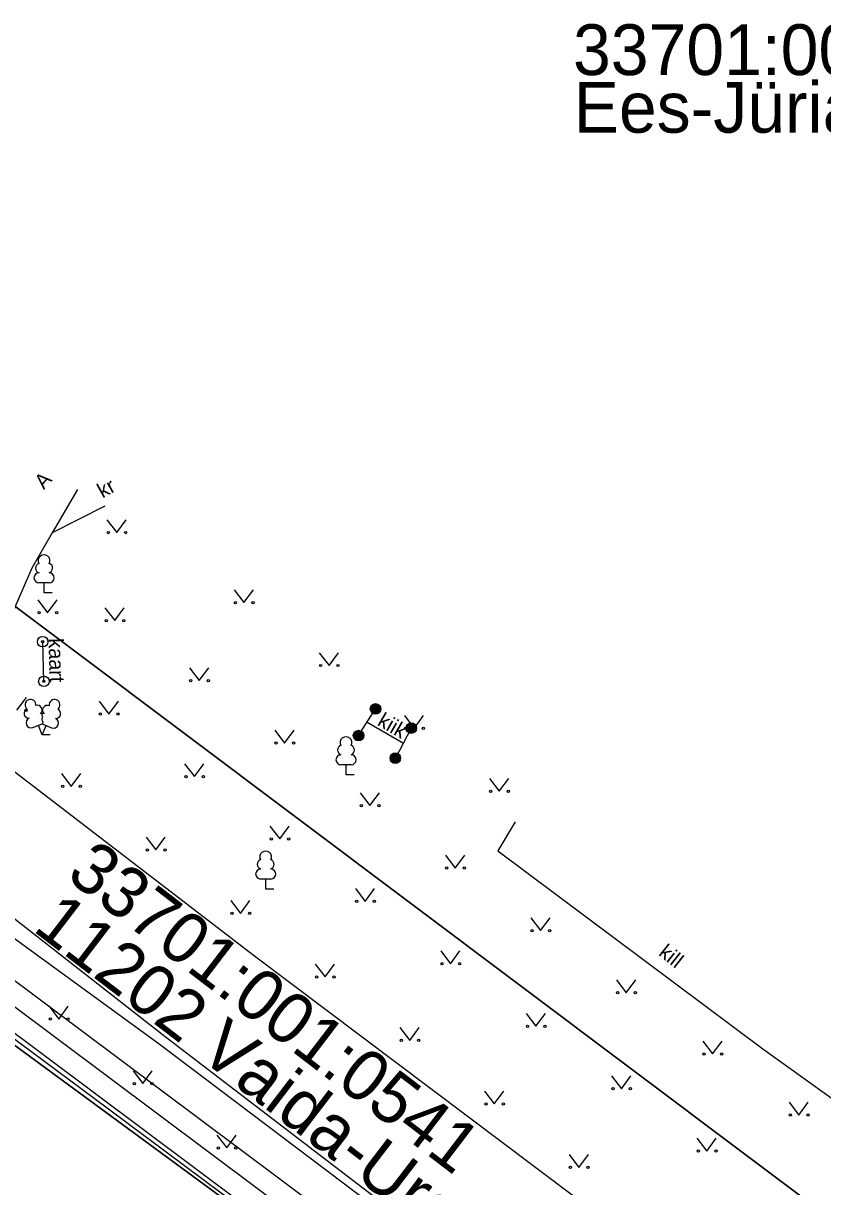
# Model space of a CAD drawing. Extents: x 554947 to 555436, y 6564938 to 6565792.
# Drawn here: x 555270.1 to 555307.9, y 6565557.2 to 6565612.2 of the extents above; entities that cross this region are included whole.
import ezdxf

# ---------------------------------------------------------------- set-up
doc = ezdxf.new("R2010")
doc.units = 0
for name, color, linetype in [('AED', 7, 'Continuous'), ('HALJASTUS', 7, 'Continuous'), ('KASUTUSALA', 7, 'Continuous'), ('LIIKLUS', 7, 'Continuous'), ('PIIR', 7, 'Continuous'), ('POST', 7, 'Continuous'), ('PR_SIDE', 7, 'Continuous'), ('PUU', 7, 'Continuous'), ('TEE', 7, 'Continuous')]:
    doc.layers.add(name, color=color, linetype=linetype)

msp = doc.modelspace()

# ---------------------------------------------------------------- linework, layer by layer
at = {"layer": 'AED'}
msp.add_lwpolyline([(555301.646, 6565540.531), (555292.158, 6565547.42), (555274.134, 6565560.859), (555261.407, 6565570.297)], dxfattribs=at)
at = {"layer": 'HALJASTUS'}
for p, q in [((555274.065, 6565588.705), (555274.529, 6565588.099)), ((555274.529, 6565588.099), (555274.974, 6565588.705)), ((555280.082, 6565585.392), (555280.545, 6565584.785)), ((555280.545, 6565584.785), (555280.991, 6565585.392)), ((555270.802, 6565584.917), (555271.265, 6565584.311)), ((555271.265, 6565584.311), (555271.711, 6565584.917)), ((555273.975, 6565584.54), (555274.438, 6565583.934)), ((555274.438, 6565583.934), (555274.884, 6565584.54)), ((555284.104, 6565582.421), (555284.567, 6565581.815)), ((555284.567, 6565581.815), (555285.013, 6565582.421)), ((555277.967, 6565581.711), (555278.43, 6565581.104)), ((555278.43, 6565581.104), (555278.876, 6565581.711)), ((555269.814, 6565579.699), (555270.26, 6565580.306)), ((555273.698, 6565580.126), (555274.162, 6565579.519)), ((555274.162, 6565579.519), (555274.607, 6565580.126)), ((555288.126, 6565579.451), (555288.589, 6565578.844)), ((555288.589, 6565578.844), (555289.035, 6565579.451)), ((555282.001, 6565578.757), (555282.464, 6565578.15)), ((555282.464, 6565578.15), (555282.91, 6565578.757)), ((555277.735, 6565577.176), (555278.199, 6565576.569)), ((555278.199, 6565576.569), (555278.644, 6565577.176)), ((555271.917, 6565576.711), (555272.38, 6565576.104)), ((555272.38, 6565576.104), (555272.826, 6565576.711)), ((555292.148, 6565576.481), (555292.611, 6565575.874)), ((555292.611, 6565575.874), (555293.057, 6565576.481)), ((555286.035, 6565575.803), (555286.499, 6565575.196)), ((555286.499, 6565575.196), (555286.944, 6565575.803)), ((555281.772, 6565574.226), (555282.236, 6565573.619)), ((555282.236, 6565573.619), (555282.681, 6565574.226)), ((555275.916, 6565573.71), (555276.38, 6565573.104)), ((555276.38, 6565573.104), (555276.825, 6565573.71)), ((555290.069, 6565572.849), (555290.533, 6565572.243)), ((555290.533, 6565572.243), (555290.978, 6565572.849)), ((555285.809, 6565571.276), (555286.273, 6565570.669)), ((555286.273, 6565570.669), (555286.718, 6565571.276)), ((555279.916, 6565570.71), (555280.379, 6565570.103)), ((555280.379, 6565570.103), (555280.825, 6565570.71)), ((555294.104, 6565569.895), (555294.567, 6565569.289)), ((555294.567, 6565569.289), (555295.013, 6565569.895)), ((555289.846, 6565568.326), (555290.31, 6565567.719)), ((555290.31, 6565567.719), (555290.755, 6565568.326)), ((555283.915, 6565567.709), (555284.379, 6565567.102)), ((555284.379, 6565567.102), (555284.824, 6565567.709)), ((555298.15, 6565566.958), (555298.613, 6565566.351)), ((555298.613, 6565566.351), (555299.059, 6565566.958)), ((555271.333, 6565565.713), (555271.796, 6565565.106)), ((555271.796, 6565565.106), (555272.242, 6565565.713)), ((555293.883, 6565565.376), (555294.347, 6565564.769)), ((555294.347, 6565564.769), (555294.792, 6565565.376)), ((555287.915, 6565564.708), (555288.378, 6565564.102)), ((555288.378, 6565564.102), (555288.824, 6565564.708)), ((555302.23, 6565564.068), (555302.693, 6565563.461)), ((555302.693, 6565563.461), (555303.139, 6565564.068)), ((555275.3, 6565562.67), (555275.764, 6565562.063)), ((555275.764, 6565562.063), (555276.209, 6565562.67)), ((555297.92, 6565562.426), (555298.384, 6565561.819)), ((555298.384, 6565561.819), (555298.829, 6565562.426)), ((555291.914, 6565561.708), (555292.378, 6565561.101)), ((555292.378, 6565561.101), (555292.823, 6565561.708)), ((555306.31, 6565561.178), (555306.773, 6565560.571)), ((555306.773, 6565560.571), (555307.219, 6565561.178)), ((555279.268, 6565559.627), (555279.731, 6565559.02)), ((555279.731, 6565559.02), (555280.177, 6565559.627)), ((555301.957, 6565559.476), (555302.421, 6565558.869)), ((555302.421, 6565558.869), (555302.866, 6565559.476)), ((555295.914, 6565558.707), (555296.377, 6565558.1)), ((555296.377, 6565558.1), (555296.823, 6565558.707))]:
    msp.add_line(p, q, dxfattribs=at)
for centre in [(555274.128, 6565588.099), (555274.956, 6565588.099), (555280.144, 6565584.785), (555280.973, 6565584.785), (555270.864, 6565584.311), (555271.693, 6565584.311), (555274.037, 6565583.934), (555274.866, 6565583.934), (555284.166, 6565581.815), (555284.995, 6565581.815), (555278.029, 6565581.104), (555278.858, 6565581.104), (555270.242, 6565579.699), (555273.761, 6565579.519), (555274.589, 6565579.519), (555288.188, 6565578.844), (555289.017, 6565578.844), (555282.063, 6565578.15), (555282.892, 6565578.15), (555277.798, 6565576.569), (555278.626, 6565576.569), (555271.979, 6565576.104), (555272.808, 6565576.104), (555292.21, 6565575.874), (555293.039, 6565575.874), (555286.098, 6565575.196), (555286.926, 6565575.196), (555281.835, 6565573.619), (555282.663, 6565573.619), (555275.979, 6565573.104), (555276.807, 6565573.104), (555290.132, 6565572.243), (555290.961, 6565572.243), (555285.872, 6565570.669), (555286.7, 6565570.669), (555279.978, 6565570.103), (555280.807, 6565570.103), (555294.166, 6565569.289), (555294.995, 6565569.289), (555289.909, 6565567.719), (555290.737, 6565567.719), (555283.978, 6565567.102), (555284.806, 6565567.102), (555298.212, 6565566.351), (555299.041, 6565566.351), (555271.395, 6565565.106), (555272.224, 6565565.106), (555293.946, 6565564.769), (555294.774, 6565564.769), (555287.977, 6565564.102), (555288.806, 6565564.102), (555302.292, 6565563.461), (555303.121, 6565563.461), (555275.363, 6565562.063), (555276.192, 6565562.063), (555297.983, 6565561.819), (555298.811, 6565561.819), (555291.977, 6565561.101), (555292.805, 6565561.101), (555306.372, 6565560.571), (555307.201, 6565560.571), (555279.33, 6565559.02), (555280.159, 6565559.02), (555302.02, 6565558.869), (555302.849, 6565558.869), (555295.976, 6565558.1), (555296.805, 6565558.1)]:
    msp.add_circle(centre, 0.055, dxfattribs=at)
at = {"layer": 'KASUTUSALA'}
msp.add_lwpolyline([(555282.937, 6565554.541), (555264.078, 6565568.633), (555259.865, 6565571.933), (555249.017, 6565580.573), (555243.622, 6565583.862), (555238.34, 6565585.678), (555238.34, 6565584.092), (555236.34, 6565584.168), (555236.34, 6565586.946), (555231.217, 6565605.702), (555233.309, 6565605.634), (555234.35, 6565605.6), (555235.803, 6565604.987), (555234.66, 6565604.12), (555233.701, 6565604.199), (555238.103, 6565588.08), (555238.166, 6565587.854), (555238.34, 6565587.793), (555244.478, 6565585.683), (555250.166, 6565582.216), (555261.104, 6565573.503), (555265.293, 6565570.221), (555284.174, 6565556.114)], dxfattribs=at)
at = {"layer": 'LIIKLUS'}
msp.add_line((555271.087, 6565581.066), (555271.031, 6565582.94), dxfattribs=at)
for centre, radius in [((555271.031, 6565582.94), 0.25), ((555271.031, 6565582.94), 0.05), ((555271.087, 6565581.066), 0.25), ((555271.087, 6565581.066), 0.05)]:
    msp.add_circle(centre, radius, dxfattribs=at)
at = {"layer": 'PIIR'}
for points in [[(555374.15, 6565660.24), (555410.9, 6565638.65), (555418.94, 6565635.85), (555435.71, 6565632.72), (555428.83, 6565620.98), (555419.65, 6565609.54), (555361.56, 6565549.57), (555350.68, 6565540.44), (555343.81, 6565536.56), (555330.71, 6565538.85), (555251.24, 6565598.48), (555234.35, 6565605.6), (555223.17, 6565668.21)], [(555144.16, 6565410.6), (555124.27, 6565454.45), (555113.82, 6565475.68), (555076.76, 6565542.38), (555065.78, 6565566.7), (555060.42, 6565583.26), (555057.22, 6565600.73), (555056.61, 6565622.91), (555063.43, 6565647.29), (555114.24, 6565634), (555129.77, 6565611.2), (555130.73, 6565621.32), (555138.66, 6565615.26), (555160.12, 6565598.86), (555193.24, 6565604.68), (555193.7, 6565602.7), (555225.47, 6565605.89), (555234.35, 6565605.6), (555251.24, 6565598.48), (555330.71, 6565538.85), (555343.81, 6565536.56), (555350.68, 6565540.44), (555361.56, 6565549.57), (555393.069, 6565582.099)], [(555393.069, 6565560.972), (555353.12, 6565523.87), (555343.14, 6565512.46), (555302.6, 6565539.71), (555242.37, 6565583.94), (555179.42, 6565586.32), (555138.98, 6565580.6), (555121.18, 6565602.26), (555116.17, 6565610.5), (555109.96, 6565624.83), (555093.56, 6565628.47), (555079.04, 6565618.4), (555074.13, 6565607.82), (555075.34, 6565593.24), (555091.74, 6565551.94), (555171.91, 6565394.64), (555191.35, 6565341.19), (555195.08, 6565294.61), (555195.28, 6565271.63), (555191.64, 6565237.48)]]:
    msp.add_lwpolyline(points, dxfattribs=at)
msp.add_lwpolyline([(555121.18, 6565602.26), (555138.98, 6565580.6), (555179.42, 6565586.32), (555242.37, 6565583.94), (555302.6, 6565539.71), (555287.77, 6565518.56), (555207.29, 6565506.14), (555200.64, 6565496.23), (555185.97, 6565502.75), (555177.68, 6565506.44), (555171.49, 6565510.85), (555162.05, 6565514.45), (555140.65, 6565513.25), (555139.49, 6565523.98), (555139.26, 6565529.51), (555141.68, 6565537.52), (555139.64, 6565543.1), (555131.01, 6565550.06), (555126.35, 6565558.74), (555119.63, 6565564.84), (555105.26, 6565587.71), (555099.5, 6565594.91), (555116.17, 6565610.5)], close=True, dxfattribs=at)
at = {"layer": 'POST'}
for points in [[(555285.962, 6565578.503), (555286.765, 6565579.763)], [(555286.364, 6565579.133), (555288.077, 6565578.147)], [(555288.455, 6565578.857), (555287.699, 6565577.437)]]:
    msp.add_lwpolyline(points, dxfattribs=at)
for centre, radius in [((555286.765, 6565579.763), 0.25), ((555286.765, 6565579.763), 0.225), ((555286.765, 6565579.763), 0.2), ((555286.765, 6565579.763), 0.175), ((555286.765, 6565579.763), 0.15), ((555286.765, 6565579.763), 0.125), ((555286.765, 6565579.763), 0.1), ((555286.765, 6565579.763), 0.075), ((555286.765, 6565579.763), 0.05), ((555286.765, 6565579.763), 0.025), ((555288.455, 6565578.857), 0.25), ((555288.455, 6565578.857), 0.225), ((555288.455, 6565578.857), 0.2), ((555288.455, 6565578.857), 0.175), ((555288.455, 6565578.857), 0.15), ((555285.962, 6565578.503), 0.25), ((555285.962, 6565578.503), 0.225), ((555285.962, 6565578.503), 0.2), ((555285.962, 6565578.503), 0.175), ((555285.962, 6565578.503), 0.15), ((555285.962, 6565578.503), 0.125), ((555285.962, 6565578.503), 0.1), ((555285.962, 6565578.503), 0.075), ((555285.962, 6565578.503), 0.05), ((555285.962, 6565578.503), 0.025), ((555288.455, 6565578.857), 0.125), ((555288.455, 6565578.857), 0.1), ((555288.455, 6565578.857), 0.075), ((555288.455, 6565578.857), 0.05), ((555288.455, 6565578.857), 0.025), ((555287.699, 6565577.437), 0.25), ((555287.699, 6565577.437), 0.225), ((555287.699, 6565577.437), 0.2), ((555287.699, 6565577.437), 0.175), ((555287.699, 6565577.437), 0.15), ((555287.699, 6565577.437), 0.125), ((555287.699, 6565577.437), 0.1), ((555287.699, 6565577.437), 0.075), ((555287.699, 6565577.437), 0.05), ((555287.699, 6565577.437), 0.025)]:
    msp.add_circle(centre, radius, dxfattribs=at)
at = {"layer": 'PR_SIDE'}
msp.add_lwpolyline([(555309.687, 6565535.684), (555303.916, 6565540.202), (555288.808, 6565550.982), (555283.555, 6565555.328), (555264.686, 6565569.427), (555260.485, 6565572.718), (555249.591, 6565581.395), (555244.05, 6565584.772), (555237.34, 6565587.08), (555232.399, 6565605.169), (555232.137, 6565606.132)], dxfattribs=at)
at = {"layer": 'PUU'}
for p, q in [((555271.335, 6565585.723), (555270.855, 6565585.723)), ((555271.095, 6565585.248), (555271.095, 6565585.723)), ((555271.475, 6565585.248), (555271.095, 6565585.248)), ((555270.569, 6565578.88), (555271.014, 6565579.055)), ((555271.014, 6565579.055), (555271.454, 6565578.875)), ((555271.009, 6565578.545), (555270.834, 6565578.985)), ((555271.009, 6565578.545), (555271.189, 6565578.985)), ((555271.389, 6565578.545), (555271.009, 6565578.545)), ((555285.608, 6565577.125), (555285.128, 6565577.125)), ((555285.368, 6565576.65), (555285.368, 6565577.125)), ((555285.748, 6565576.65), (555285.368, 6565576.65)), ((555281.811, 6565571.725), (555281.331, 6565571.725)), ((555281.571, 6565571.25), (555281.571, 6565571.725)), ((555281.951, 6565571.25), (555281.571, 6565571.25))]:
    msp.add_line(p, q, dxfattribs=at)
msp.add_lwpolyline([(555271.014, 6565579.55), (555270.994, 6565579.475), (555270.994, 6565579.455), (555271.004, 6565579.425), (555271.024, 6565579.39), (555271.029, 6565579.37), (555271.014, 6565579.335), (555270.989, 6565579.285), (555270.984, 6565579.26), (555270.989, 6565579.245), (555270.999, 6565579.215), (555271.034, 6565579.155), (555271.039, 6565579.135), (555271.034, 6565579.115), (555271.019, 6565579.08), (555271.014, 6565579.055)], dxfattribs=at)
for centre, radius, start, end in [((555271.095, 6565586.768), 0.277, 332.5799, 207.4201), ((555270.858, 6565585.96), 0.238, 90.0016, 269.3953), ((555270.925, 6565586.42), 0.233, 109.0217, 253.1415), ((555271.265, 6565586.42), 0.233, 286.8508, 70.9859), ((555271.333, 6565585.96), 0.238, 270.6047, 89.9984), ((555270.452, 6565579.96), 0.256, 111.5027, 232.5173), ((555270.452, 6565579.96), 0.256, 350.4856, 111.5002), ((555271.588, 6565579.951), 0.256, 67.6168, 188.6314), ((555271.588, 6565579.951), 0.256, 306.5997, 67.6143), ((555270.378, 6565579.548), 0.224, 111.4304, 274.4987), ((555270.787, 6565579.709), 0.224, 308.5041, 111.5725), ((555271.013, 6565579.313), 0.237, 66.7655, 111.5015), ((555271.25, 6565579.704), 0.225, 67.7016, 230.5126), ((555271.656, 6565579.538), 0.224, 264.6183, 67.6866), ((555270.483, 6565579.104), 0.237, 111.5014, 291.5004), ((555271.544, 6565579.096), 0.237, 247.6166, 67.6155), ((555285.368, 6565578.17), 0.277, 332.5799, 207.4201), ((555285.198, 6565577.823), 0.233, 109.0217, 253.1415), ((555285.538, 6565577.823), 0.233, 286.8508, 70.9859), ((555285.131, 6565577.362), 0.238, 90.0016, 269.3953), ((555285.606, 6565577.362), 0.238, 270.6047, 89.9984), ((555281.571, 6565572.77), 0.277, 332.5799, 207.4201), ((555281.401, 6565572.423), 0.233, 109.0217, 253.1415), ((555281.741, 6565572.423), 0.233, 286.8508, 70.9859), ((555281.334, 6565571.963), 0.238, 90.0016, 269.3953), ((555281.809, 6565571.963), 0.238, 270.6047, 89.9984)]:
    msp.add_arc(centre, radius, start, end, dxfattribs=at)
at = {"layer": 'TEE'}
msp.add_line((555273.963, 6565589.336), (555271.484, 6565588.076), dxfattribs=at)
for points in [[(555309.906, 6565538.03), (555305.168, 6565541.808), (555305.066, 6565542.334), (555294.766, 6565550.531), (555276.823, 6565564.276), (555265.732, 6565572.927), (555259.684, 6565577.587), (555254.787, 6565581.289), (555247.931, 6565586.532), (555243.893, 6565589.125), (555239.934, 6565591.048), (555235.042, 6565592.642), (555234.652, 6565590.428), (555233.978, 6565588.723)], [(555272.683, 6565590.134), (555271.484, 6565588.076), (555270.516, 6565586.416), (555269.723, 6565584.609), (555268.981, 6565582.24), (555268.55, 6565578.954), (555269.504, 6565576.952), (555281.044, 6565568.103), (555297.768, 6565555.508), (555316.66, 6565541.129), (555323.074, 6565536.252), (555328.036, 6565533.009), (555332.837, 6565530.879), (555337.611, 6565529.695), (555343.363, 6565529.946), (555348.456, 6565531.532), (555353.801, 6565534.677), (555358.561, 6565538.499)], [(555304.166, 6565537.744), (555304.47, 6565538.257), (555305.035, 6565540.465), (555305.168, 6565541.808), (555294.581, 6565550.293), (555276.533, 6565563.926), (555265.084, 6565572.259), (555259.201, 6565577.119), (555257.995, 6565576.697)], [(555293.358, 6565574.435), (555292.541, 6565573.051), (555305.07, 6565563.708), (555310.251, 6565559.992), (555311.005, 6565561)]]:
    msp.add_lwpolyline(points, dxfattribs=at)

# ---------------------------------------------------------------- texts
at = {"layer": 'LIIKLUS'}
msp.add_text('kaart', height=0.7, rotation=271.6725, dxfattribs=at).set_placement((555271.304, 6565583.091))
at = {"layer": 'PIIR'}
for s, p in [('33701:001:0413', (555296.098, 6565609.713)), ('Ees-Jüriantsu', (555296.128, 6565606.99))]:
    msp.add_text(s, height=2.4, dxfattribs=at).set_placement(p)
for s, p in [('33701:001:0541', (555272.073, 6565571.791)), ('11202 Vaida-Urge tee', (555270.504, 6565569.319))]:
    msp.add_text(s, height=2.4, rotation=322.5897, dxfattribs=at).set_placement(p)
at = {"layer": 'POST'}
msp.add_text('kiik', height=0.7, rotation=330.0443, dxfattribs=at).set_placement((555286.805, 6565579.018))
at = {"layer": 'TEE'}
for s, rotation, p in [('A', 47.4618, (555271.085, 6565590.108)), ('kr', 29.2233, (555273.858, 6565589.703)), ('kill', 321.6091, (555300.1, 6565568.154))]:
    msp.add_text(s, height=0.7, rotation=rotation, dxfattribs=at).set_placement(p)

doc.saveas('drawing.dxf')
